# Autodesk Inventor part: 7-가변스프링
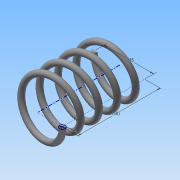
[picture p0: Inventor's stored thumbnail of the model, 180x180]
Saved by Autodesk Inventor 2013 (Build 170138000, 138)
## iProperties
Created: 2015-03
Part Number: 7-가변스프링
Material: 강철, 탄소
Document SubType Name: Modeling
Designer: Administrator
Density: 7.87 g/cm^3
Mass: 48.2733 g
Surface Area: 62.0009 cm^2
Volume: 6.13384 cm^3
Author: Administrator
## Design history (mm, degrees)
sketch "스케치1"
  geometry: L1 (0, 0)-(17.5, 0); L2 (17.5, 0)-(17.5, 43.5); L3 (17.5, 43.5)-(0, 43.5); L4 (0, 43.5)-(0, 0); C1 r 2 at (17.5, 0)
  constraints: 8 end point, 2 parallel, 1 centre point, 1 coincident, 1 horizontal, 1 perpendicular
  dimensions: "d0" = 4 diameter of C1; "d2" = 43.5 distance of L1.end L2.end (derived); "d3" = 35 diameter of L2 L4
feature "코일1" sketch "스케치1" pitch "d4" = 10; turns "d6" = 4.5; dims "d5" = 43.5 (= d2), "d7" = 0, angle "d8" = 90 deg, angle "d9" = 90 deg, "d10" = 0, "d11" = 0
sketch "스케치2"
  geometry: L1 (-19.5, 0)-(-15.5, 0) reference; 1 further point
  constraints: 1 horizontal alignment
extrude "돌출1" cut sketch "스케치2" stored distance "d12" = 10; taper "d13" = 0 deg
node "작업 평면1"
sketch "스케치3"
  geometry: L1 (-19.5, 0)-(-15.5, 0) reference; 1 further point
  constraints: 1 horizontal alignment
extrude "돌출2" cut sketch "스케치3" stored distance "d15" = 10; taper "d16" = 0 deg
node "솔리드1"
node "절단 모서리 투영1"
node "절단 모서리 투영2"
other parameters: "d14" = -43.5 (= -d2)
